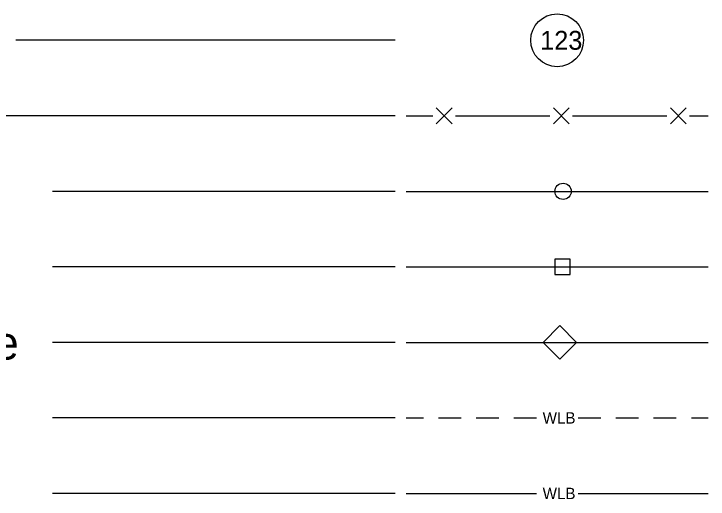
# Model space of a CAD drawing. Extents: x 811508 to 813252, y 647626 to 648754.
# Drawn here: x 811728.4 to 811918.8, y 648332 to 648465 of the extents above; entities that cross this region are included whole.
import ezdxf

# ---------------------------------------------------------------- set-up
doc = ezdxf.new("R2010")
doc.units = 0
doc.layers.add('Sheet_Symbology', color=7, linetype='Continuous')

msp = doc.modelspace()

# ---------------------------------------------------------------- linework, layer by layer
at = {"layer": 'Sheet_Symbology'}
for p, q in [((811832.99, 648457.78), (811728.99, 648457.78)), ((811844.24, 648434.91), (811848.59, 648439.25)), ((811848.59, 648434.91), (811844.24, 648439.25)), ((811876.33, 648434.91), (811880.67, 648439.25)), ((811880.67, 648434.91), (811876.33, 648439.25)), ((811908.41, 648434.91), (811912.76, 648439.25)), ((811912.76, 648434.91), (811908.41, 648439.25)), ((811832.99, 648437.08), (811682.8, 648437.08)), ((811835.96, 648437.08), (811843.31, 648437.08)), ((811849.52, 648437.08), (811862.46, 648437.08)), ((811862.46, 648437.08), (811875.39, 648437.08)), ((811881.6, 648437.08), (811894.54, 648437.08)), ((811894.54, 648437.08), (811907.48, 648437.08)), ((811913.69, 648437.08), (811918.76, 648437.08)), ((811832.99, 648416.38), (811738.97, 648416.38)), ((811835.96, 648416.38), (811918.76, 648416.38)), ((811835.96, 648416.38), (811918.76, 648416.38)), ((811832.99, 648395.68), (811738.97, 648395.68)), ((811835.96, 648395.68), (811918.76, 648395.68)), ((811835.96, 648395.68), (811918.76, 648395.68)), ((811832.99, 648374.98), (811738.97, 648374.98)), ((811835.96, 648374.98), (811918.76, 648374.98)), ((811835.96, 648374.98), (811918.76, 648374.98)), ((811832.99, 648354.28), (811738.97, 648354.28)), ((811835.96, 648354.28), (811840.7, 648354.28)), ((811844.84, 648354.28), (811851.05, 648354.28)), ((811855.19, 648354.28), (811861.4, 648354.28)), ((811865.54, 648354.28), (811871.75, 648354.28)), ((811883.13, 648354.28), (811889.34, 648354.28)), ((811893.48, 648354.28), (811899.69, 648354.28)), ((811903.83, 648354.28), (811910.04, 648354.28)), ((811914.18, 648354.28), (811918.76, 648354.28)), ((811832.99, 648333.58), (811738.97, 648333.58)), ((811832.99, 648333.58), (811738.97, 648333.58)), ((811835.96, 648333.58), (811871.75, 648333.58)), ((811883.13, 648333.58), (811918.76, 648333.58))]:
    msp.add_line(p, q, dxfattribs=at)
for points in [[(811876.71, 648393.56), (811880.96, 648393.56), (811880.96, 648397.8), (811876.71, 648397.8)], [(811878.09, 648370.43), (811882.64, 648374.98), (811878.09, 648379.59), (811873.53, 648374.98)]]:
    msp.add_lwpolyline(points, close=True, dxfattribs=at)
for centre, radius in [((811877.36, 648457.78), 7.24), ((811878.99, 648416.38), 2.23)]:
    msp.add_circle(centre, radius, dxfattribs=at)

# ---------------------------------------------------------------- texts
for s, height, p in [('123', 5.175, (811872.73, 648455.19)), ('Proposed Barbed Wire Fence', 9.056, (811570.23, 648370.28)), ('WLB', 3.105, (811873.4, 648352.73)), ('WLB', 3.105, (811873.4, 648332.03))]:
    msp.add_text(s, height=height, dxfattribs=at).set_placement(p)

doc.saveas('drawing.dxf')
